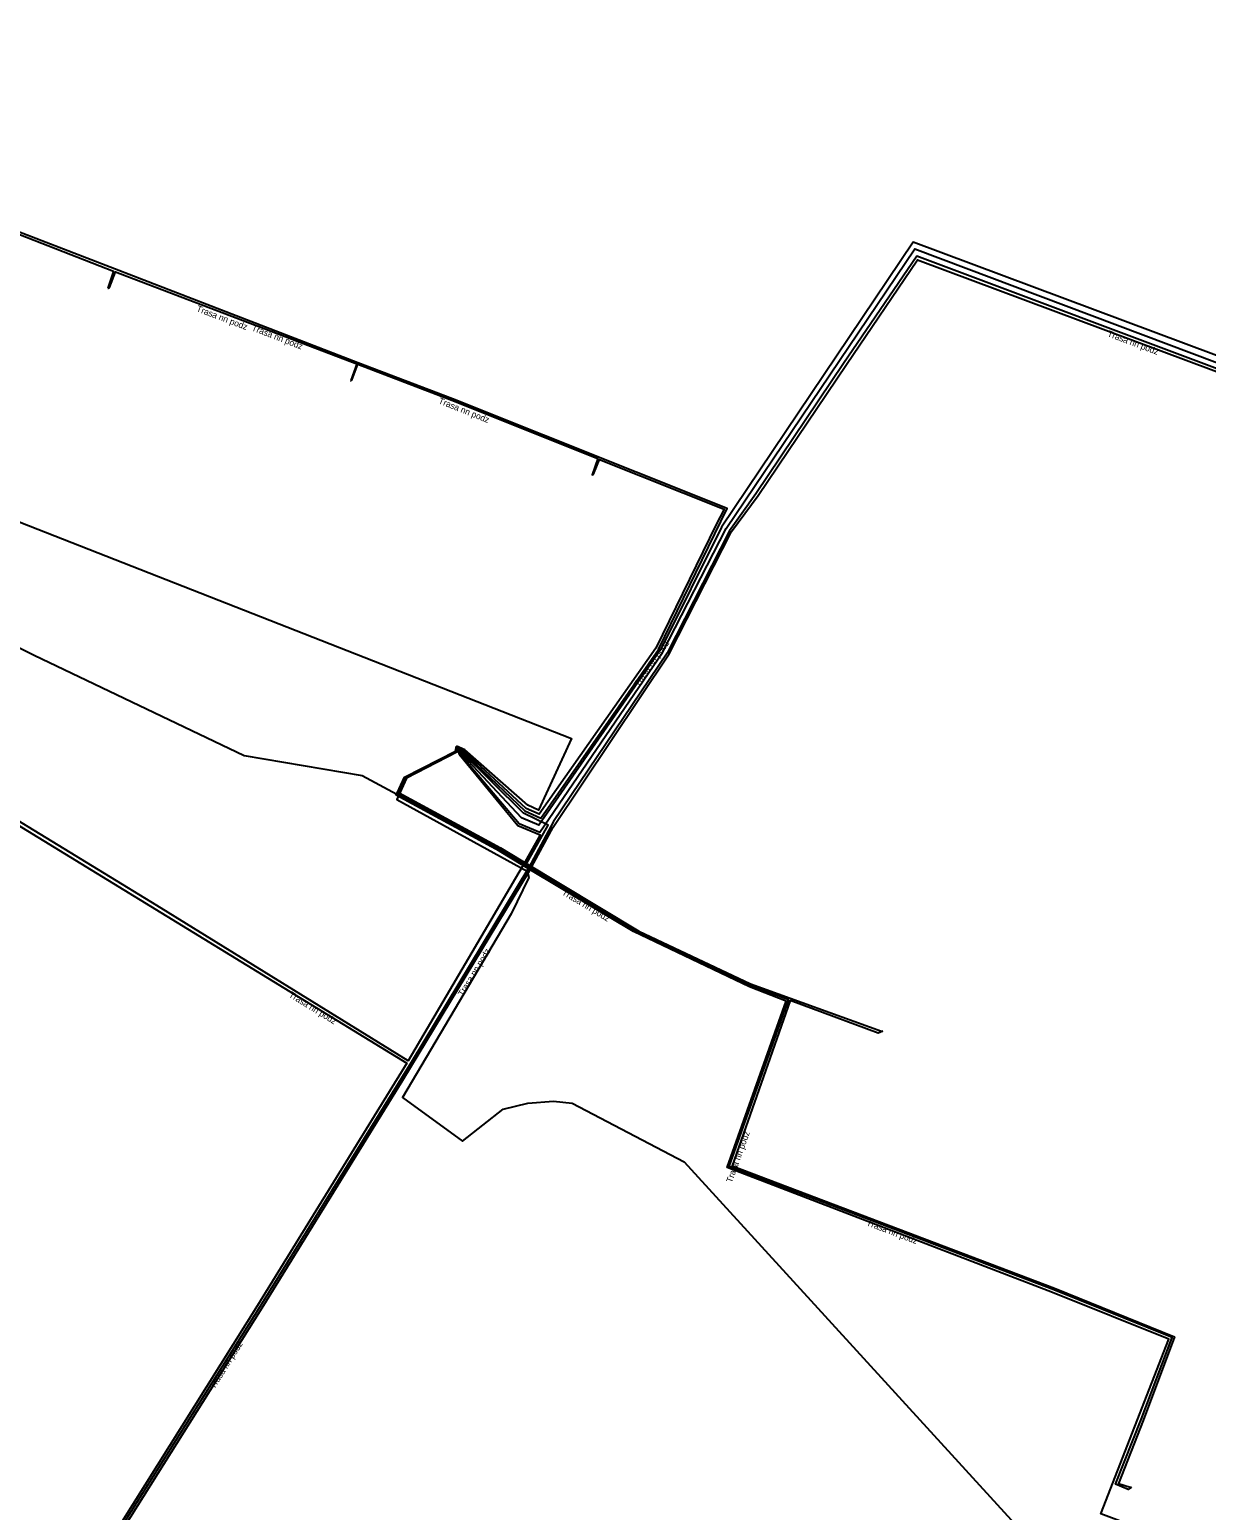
# Model space of a CAD drawing. Extents: x -875087 to -874407, y -1056142 to -1055396.
# Drawn here: x -874839.3 to -874745.8, y -1055781.1 to -1055663.5 of the extents above; entities that cross this region are included whole.
import ezdxf

# ---------------------------------------------------------------- set-up
doc = ezdxf.new("R2010")
doc.units = 0
for name, color, linetype in [('Popiskový text - Ostatní atributy Trasy', 7, 'Continuous'), ('Spojnice NN', 7, 'Continuous'), ('Spojnice VN', 7, 'Continuous')]:
    doc.layers.add(name, color=color, linetype=linetype)

msp = doc.modelspace()

# ---------------------------------------------------------------- linework, layer by layer
at = {"layer": 'Spojnice NN'}
for points in [[(-874882.28, -1055663.5), (-874882.36, -1055663.59), (-874882.36, -1055663.82), (-874882.76, -1055666.65), (-874872.96, -1055689.73), (-874796.22, -1055719.8), (-874798.83, -1055725.48), (-874799.67, -1055725.09), (-874804.68, -1055720.7), (-874805.36, -1055720.41)], [(-874805.36, -1055720.41), (-874804.9, -1055720.8), (-874799.91, -1055725.54), (-874798.64, -1055726.13), (-874789.31, -1055712.72), (-874783.85, -1055701.53), (-874805.68, -1055692.82), (-874813.18, -1055689.95), (-874832.53, -1055682.5), (-874851.52, -1055675.19), (-874865.05, -1055669.73), (-874866.37, -1055673.2), (-874866.62, -1055673.84), (-874882.43, -1055666.59), (-874882.1, -1055663.85), (-874882.28, -1055663.5)], [(-874852.1, -1055676.64), (-874852.08, -1055676.64), (-874851.97, -1055676.56), (-874851.55, -1055675.3), (-874832.62, -1055682.67), (-874833.06, -1055684.02), (-874833.07, -1055684.04)], [(-874671.63, -1055675.74), (-874670.33, -1055676.31), (-874664.47, -1055677.9), (-874660.5, -1055679.61), (-874654.24, -1055709.33), (-874658.68, -1055722.79), (-874695.05, -1055709.61), (-874743, -1055691.15), (-874768.77, -1055681.49), (-874774.59, -1055690.01), (-874781.56, -1055700.37), (-874783.65, -1055703.3), (-874788.62, -1055713.02), (-874797.64, -1055726.39), (-874799.59, -1055730.03), (-874808.94, -1055745.54), (-874820.99, -1055764.94), (-874838.65, -1055793.01), (-874841.25, -1055791.16), (-874841.27, -1055791.14)], [(-874838.49, -1055793.12), (-874820.8, -1055765.01), (-874809.61, -1055746.92), (-874799.54, -1055730.32), (-874797.66, -1055726.83), (-874788.45, -1055713.06), (-874783.51, -1055703.37), (-874781.37, -1055700.5), (-874774.35, -1055690.1), (-874768.72, -1055681.78), (-874742.98, -1055691.38), (-874743.1, -1055691.32), (-874695.15, -1055709.78), (-874695.09, -1055709.83), (-874658.86, -1055722.94), (-874654.42, -1055709.31), (-874658.57, -1055689.33), (-874660.63, -1055679.72), (-874664.59, -1055678.06), (-874670.38, -1055676.41), (-874671.63, -1055675.74)], [(-874833.07, -1055684.04), (-874833.04, -1055684.04), (-874832.93, -1055683.98), (-874832.44, -1055682.73), (-874813.28, -1055690.03), (-874813.76, -1055691.37), (-874813.77, -1055691.38)], [(-874813.77, -1055691.38), (-874813.74, -1055691.38), (-874813.68, -1055691.35), (-874813.18, -1055690.06), (-874805.71, -1055692.92), (-874794.11, -1055697.55), (-874794.58, -1055698.85), (-874794.58, -1055698.85)], [(-874794.58, -1055698.85), (-874794.57, -1055698.86), (-874794.47, -1055698.81), (-874793.98, -1055697.63), (-874784.09, -1055701.58), (-874784.71, -1055702.81), (-874789.5, -1055712.63), (-874798.78, -1055725.82), (-874799.81, -1055725.36), (-874804.85, -1055720.71), (-874805.36, -1055720.41)], [(-874805.36, -1055720.41), (-874805.14, -1055721.03), (-874800.48, -1055726.7), (-874798.71, -1055727.46), (-874800.13, -1055730), (-874809.2, -1055745.39), (-874829.16, -1055733.07), (-874841.67, -1055725.43), (-874845.42, -1055731.72), (-874845.94, -1055731.88)], [(-874661.58, -1055841.69), (-874661.36, -1055841.68), (-874657.76, -1055837.1), (-874664.35, -1055802.71), (-874686.55, -1055806.7), (-874754.15, -1055781.37), (-874748.75, -1055767.51), (-874757.99, -1055763.79), (-874783.84, -1055753.86), (-874779.16, -1055740.65), (-874782.08, -1055739.51), (-874791.28, -1055735.13), (-874799.31, -1055730.33), (-874801.93, -1055728.75), (-874810.14, -1055724.3), (-874810.06, -1055724.13), (-874809.49, -1055722.88), (-874808.09, -1055722.15), (-874805.44, -1055720.81), (-874805.36, -1055720.41)], [(-874805.36, -1055720.41), (-874805.33, -1055720.87), (-874809.32, -1055722.96), (-874810.1, -1055724.63), (-874799.74, -1055730.33), (-874799.61, -1055730.84), (-874801.01, -1055733.71), (-874809.65, -1055748.3), (-874804.87, -1055751.77), (-874801.65, -1055749.24), (-874799.68, -1055748.77), (-874797.65, -1055748.61), (-874796.15, -1055748.77), (-874787.25, -1055753.42), (-874759.32, -1055784)], [(-874751.71, -1055779.25), (-874751.97, -1055779.43), (-874752.97, -1055779.02), (-874750.94, -1055773.88), (-874748.49, -1055767.38), (-874757.87, -1055763.58), (-874783.67, -1055753.78), (-874778.98, -1055740.56), (-874782.03, -1055739.4), (-874791.12, -1055735.07), (-874800.21, -1055729.61), (-874801.85, -1055728.57), (-874810, -1055724.16), (-874809.45, -1055722.91), (-874805.4, -1055720.82), (-874805.36, -1055720.41)], [(-874805.36, -1055720.41), (-874805.34, -1055720.85), (-874809.38, -1055722.93), (-874809.91, -1055724.1), (-874801.85, -1055728.47), (-874800.11, -1055729.55), (-874790.86, -1055735.11), (-874781.98, -1055739.29), (-874771.59, -1055743.04), (-874771.48, -1055743.05)], [(-874845.94, -1055731.88), (-874845.02, -1055731.73), (-874841.56, -1055725.84), (-874809.29, -1055745.59), (-874821.17, -1055764.82), (-874859.09, -1055825.25), (-874862.21, -1055821.34), (-874862.58, -1055821)], [(-874771.48, -1055743.05), (-874771.83, -1055743.19), (-874778.83, -1055740.61), (-874783.44, -1055753.73), (-874757.83, -1055763.44), (-874748.29, -1055767.31), (-874750.78, -1055773.96), (-874752.74, -1055778.97), (-874751.81, -1055779.25), (-874751.71, -1055779.25)]]:
    msp.add_lwpolyline(points, dxfattribs=at)
at = {"layer": 'Spojnice VN'}
for points in [[(-874671.56, -1055675.74), (-874664.83, -1055679.35), (-874642.85, -1055690.87), (-874653.48, -1055708.53), (-874658.01, -1055722.19), (-874694.8, -1055708.8), (-874742.75, -1055690.2), (-874769.05, -1055680.37), (-874784.29, -1055703), (-874789.15, -1055712.76), (-874798.81, -1055726.69), (-874800.18, -1055726.09), (-874805.16, -1055720.78), (-874805.36, -1055720.41)], [(-874805.36, -1055720.41), (-874805.24, -1055720.8), (-874800.38, -1055726.55), (-874798.72, -1055727.23), (-874788.98, -1055712.98), (-874783.92, -1055703.11), (-874768.94, -1055680.92), (-874742.85, -1055690.72), (-874695, -1055709.1), (-874658.06, -1055722.54), (-874659.97, -1055728.95), (-874656.4, -1055730.43)], [(-874889.46, -1055699.29), (-874882.83, -1055691.67), (-874874.5, -1055695.2), (-874838.9, -1055713.19), (-874822.22, -1055721.14), (-874812.85, -1055722.73), (-874801.88, -1055728.65), (-874799.88, -1055729.89), (-874798.06, -1055726.69), (-874800.02, -1055725.74), (-874805.04, -1055720.78), (-874805.36, -1055720.41)]]:
    msp.add_lwpolyline(points, dxfattribs=at)

# ---------------------------------------------------------------- texts
at = {"layer": 'Popiskový text - Ostatní atributy Trasy'}
for rotation, p in [(339.1397, (-874826.06, -1055685.85)), (338.9381, (-874821.67, -1055687.38)), (339.452, (-874753.67, -1055687.84)), (338.2586, (-874806.83, -1055693.17)), (54.8681, (-874790.88, -1055715.72)), (329.0071, (-874797.02, -1055732.16)), (58.7553, (-874804.84, -1055740.32)), (328.3241, (-874818.72, -1055740.28)), (70.467, (-874783.46, -1055755.12)), (339.2443, (-874772.82, -1055758.45)), (57.8862, (-874824.59, -1055771.5))]:
    msp.add_text('Trasa nn podz', height=0.5, rotation=rotation, dxfattribs=at).set_placement(p)

doc.saveas('drawing.dxf')
